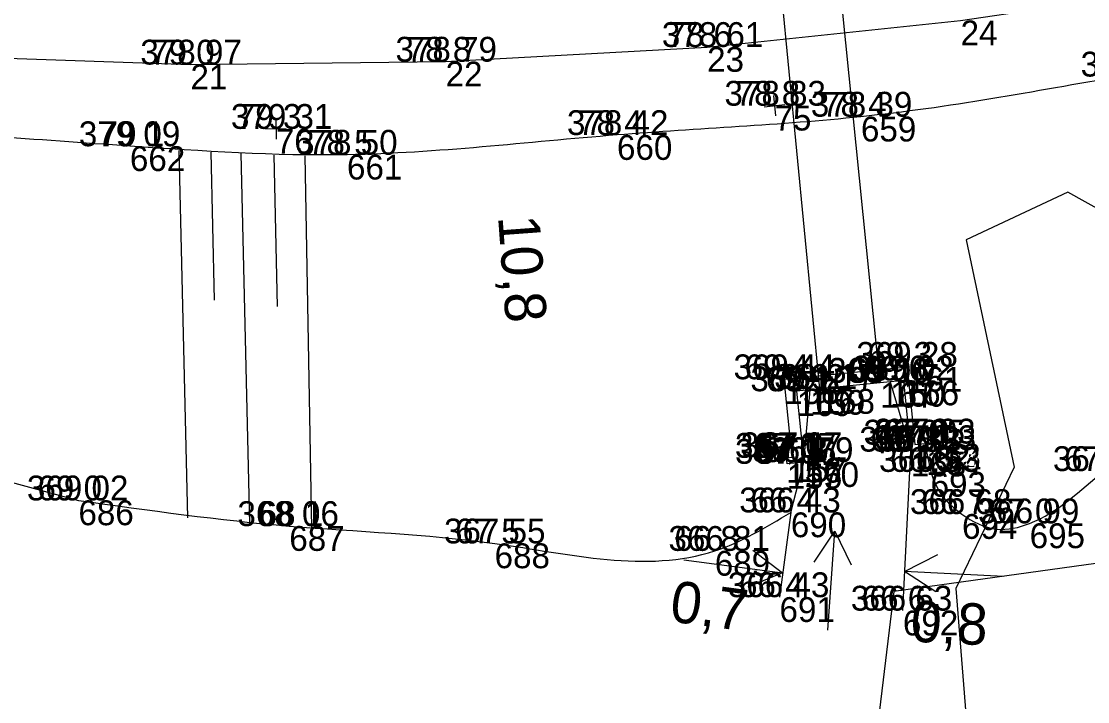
# Model space of a CAD drawing. Extents: x -514509 to -512782, y -1144610 to -1143439.
# Drawn here: x -512888.6 to -512837, y -1143668.1 to -1143635.2 of the extents above; entities that cross this region are included whole.
import ezdxf

# ---------------------------------------------------------------- set-up
doc = ezdxf.new("R2010")
doc.units = 0
for name, color, linetype in [('Vrstva 10', 7, 'Continuous'), ('Vrstva 11', 7, 'Continuous'), ('Vrstva 12', 7, 'Continuous'), ('Vrstva 35', 7, 'Continuous'), ('Vrstva 57', 7, 'Continuous'), ('Vrstva 58', 7, 'Continuous'), ('Vrstva 59', 7, 'Continuous'), ('Vrstva 6', 7, 'Continuous'), ('Vrstva 60', 7, 'Continuous'), ('Vrstva 8', 7, 'Continuous')]:
    doc.layers.add(name, color=color, linetype=linetype)

msp = doc.modelspace()

# ---------------------------------------------------------------- linework, layer by layer
at = {"layer": 'Vrstva 10'}
for p, q in [((-512853.178, -1143660.816), (-512851.751, -1143661.915)), ((-512844.324, -1143662.824), (-512845.836, -1143661.847))]:
    msp.add_line(p, q, dxfattribs=at)
for points in [[(-512782.341, -1143656.666), (-512796.89, -1143661.893), (-512815.309, -1143658.506), (-512846.358, -1143662.813), (-512847.692, -1143673.887), (-512850.552, -1143675.414), (-512874.542, -1143673.507), (-512907.663, -1143668.822), (-512937.442, -1143663.927), (-512942.033, -1143670.511), (-512944.784, -1143662.787), (-512958.978, -1143654.892), (-512977.284, -1143642.016), (-512997.25, -1143628.575), (-513034.474, -1143613.524), (-513050.89, -1143616.331), (-513050.251, -1143607.386), (-513065.331, -1143600.696), (-513084.436, -1143602.206), (-513086.215, -1143618.123), (-513093.877, -1143618.167), (-513107.772, -1143623.787)], [(-512782.341, -1143656.666), (-512796.89, -1143661.893), (-512815.309, -1143658.506), (-512846.358, -1143662.813), (-512847.692, -1143673.887), (-512850.552, -1143675.414), (-512874.542, -1143673.507), (-512907.663, -1143668.822), (-512937.442, -1143663.927), (-512942.033, -1143670.511), (-512944.784, -1143662.787), (-512958.978, -1143654.892), (-512977.284, -1143642.016), (-512997.25, -1143628.575), (-513034.474, -1143613.524), (-513050.89, -1143616.331), (-513050.251, -1143607.386), (-513065.331, -1143600.696), (-513084.436, -1143602.206), (-513086.215, -1143618.123), (-513093.877, -1143618.167), (-513107.772, -1143623.787)], [(-512880.948, -1143641.486), (-512880.52, -1143659.253)], [(-512879.401, -1143641.562), (-512879.237, -1143648.731)], [(-512877.937, -1143641.637), (-512877.524, -1143659.543)], [(-512876.35, -1143641.712), (-512876.182, -1143649.035)], [(-512874.844, -1143641.75), (-512874.529, -1143659.75)], [(-512845.919, -1143663.74), (-512845.531, -1143656.051)], [(-512845.531, -1143656.051), (-512844.799, -1143655.978)], [(-512844.799, -1143655.978), (-512844.576, -1143657.027)], [(-512851.339, -1143658.988), (-512850.718, -1143656.557)], [(-512892.217, -1143656.68), (-512885.803, -1143658.408)], [(-512851.339, -1143658.988), (-512851.888, -1143663.089)], [(-512856.509, -1143661.279), (-512851.751, -1143661.915), (-512853.417, -1143662.6)], [(-512841.043, -1143662.089), (-512845.836, -1143661.847), (-512844.233, -1143661.026)]]:
    msp.add_lwpolyline(points, dxfattribs=at)
for points in [[(-512790.897, -1143626.621), (-512793.153, -1143627.37), (-512801.979, -1143630.109), (-512814.416, -1143633.347), (-512816.803, -1143634.041), (-512819.178, -1143634.783), (-512823.981, -1143636.052), (-512829.685, -1143637.032), (-512835.405, -1143637.911), (-512841.665, -1143638.994), (-512847.953, -1143639.855), (-512859.749, -1143640.736), (-512872.808, -1143641.694), (-512883.31, -1143641.277), (-512896.82, -1143640.272), (-512913.118, -1143638.801), (-512924.825, -1143637.396), (-512937.268, -1143634.907), (-512939.41, -1143634.383), (-512941.531, -1143633.79), (-512945.755, -1143632.503)], [(-512844.576, -1143657.027), (-512844.04, -1143658.152), (-512843.598, -1143658.634), (-512843.062, -1143659.073), (-512841.392, -1143659.8), (-512839.792, -1143659.523), (-512836.217, -1143656.986), (-512830.883, -1143653.422), (-512826.439, -1143651.71), (-512824.084, -1143651.268), (-512821.716, -1143650.935), (-512819.397, -1143650.852), (-512817.055, -1143651.011), (-512814.731, -1143651.09), (-512812.465, -1143650.761), (-512801.811, -1143647.536), (-512792.751, -1143644.919), (-512786.376, -1143642.498)], [(-512885.803, -1143658.408), (-512875.601, -1143659.652), (-512865.666, -1143660.49), (-512855.017, -1143660.853), (-512851.339, -1143658.988)]]:
    msp.add_spline(points, degree=3, dxfattribs=at)
at = {"layer": 'Vrstva 12'}
for p, q in [((-512852.183, -1143638.822), (-512852.08, -1143639.817)), ((-512852.629, -1143639.371), (-512851.634, -1143639.268)), ((-512876.251, -1143639.936), (-512876.24, -1143640.935)), ((-512876.745, -1143640.441), (-512875.746, -1143640.43))]:
    msp.add_line(p, q, dxfattribs=at)
at = {"layer": 'Vrstva 35'}
msp.add_line((-512850.216, -1143661.392), (-512849.206, -1143659.901), dxfattribs=at)
msp.add_lwpolyline([(-512849.552, -1143664.689), (-512849.206, -1143659.901), (-512848.42, -1143661.522)], dxfattribs=at)
at = {"layer": 'Vrstva 6'}
for points in [[(-512853.29, -1143618.47), (-512849.95, -1143653.02)], [(-512847.02, -1143652.72), (-512850.51, -1143618.22)], [(-512923.252, -1143633.493), (-512918.011, -1143634.327), (-512906.183, -1143635.855), (-512893.885, -1143636.856), (-512880.383, -1143637.329), (-512868.04, -1143637.187), (-512855.387, -1143636.484), (-512843.127, -1143635.205), (-512831.29, -1143633.444), (-512825.879, -1143632.464), (-512813.965, -1143629.91), (-512805.054, -1143627.626), (-512792.68, -1143623.924), (-512791.757, -1143623.602)], [(-512846.533, -1143652.676), (-512845.531, -1143656.051)], [(-512850.718, -1143656.557), (-512850.413, -1143653.065)]]:
    msp.add_lwpolyline(points, dxfattribs=at)
msp.add_lwpolyline([(-512851.526, -1143656.638), (-512851.556, -1143656.349), (-512851.277, -1143656.321), (-512851.656, -1143652.552), (-512850.184, -1143652.403), (-512847.325, -1143652.116), (-512845.717, -1143651.955), (-512845.339, -1143655.71), (-512844.831, -1143655.659), (-512844.799, -1143655.978), (-512845.531, -1143656.051), (-512845.877, -1143652.607), (-512847.024, -1143652.723), (-512849.947, -1143653.017), (-512851.062, -1143653.129), (-512850.718, -1143656.557)], close=True, dxfattribs=at)
msp.add_lwpolyline([(-512851.526, -1143656.638), (-512851.556, -1143656.349), (-512851.277, -1143656.321), (-512851.656, -1143652.552), (-512850.184, -1143652.403), (-512847.325, -1143652.116), (-512845.717, -1143651.955), (-512845.339, -1143655.71), (-512844.831, -1143655.659), (-512844.799, -1143655.978), (-512845.531, -1143656.051), (-512845.877, -1143652.607), (-512847.024, -1143652.723), (-512849.947, -1143653.017), (-512851.062, -1143653.129), (-512850.718, -1143656.557)], close=True, dxfattribs=at)
at = {"layer": 'Vrstva 60'}
for p, q in [((-512855.39, -1143636.48), (-512855.39, -1143636.48)), ((-512880.38, -1143637.33), (-512880.38, -1143637.33)), ((-512868.04, -1143637.19), (-512868.04, -1143637.19)), ((-512852.13, -1143639.32), (-512852.13, -1143639.32)), ((-512847.95, -1143639.85), (-512847.95, -1143639.85)), ((-512876.25, -1143640.44), (-512876.25, -1143640.44)), ((-512859.75, -1143640.74), (-512859.75, -1143640.74)), ((-512883.31, -1143641.28), (-512883.31, -1143641.28)), ((-512872.81, -1143641.69), (-512872.81, -1143641.69)), ((-512845.72, -1143651.95), (-512845.72, -1143651.95)), ((-512851.66, -1143652.55), (-512851.66, -1143652.55)), ((-512849.95, -1143653.02), (-512849.95, -1143653.02)), ((-512847.02, -1143652.72), (-512847.02, -1143652.72)), ((-512846.533, -1143652.676), (-512846.533, -1143652.676)), ((-512845.88, -1143652.61), (-512845.88, -1143652.61)), ((-512851.06, -1143653.13), (-512851.06, -1143653.13)), ((-512850.413, -1143653.065), (-512850.413, -1143653.065)), ((-512845.53, -1143656.05), (-512845.53, -1143656.05)), ((-512845.34, -1143655.71), (-512845.34, -1143655.71)), ((-512844.83, -1143655.66), (-512844.83, -1143655.66)), ((-512844.8, -1143655.98), (-512844.8, -1143655.98)), ((-512851.56, -1143656.35), (-512851.56, -1143656.35)), ((-512851.53, -1143656.64), (-512851.53, -1143656.64)), ((-512851.28, -1143656.32), (-512851.28, -1143656.32)), ((-512850.72, -1143656.56), (-512850.72, -1143656.56)), ((-512844.58, -1143657.03), (-512844.58, -1143657.03)), ((-512885.8, -1143658.41), (-512885.8, -1143658.41)), ((-512851.34, -1143658.99), (-512851.34, -1143658.99)), ((-512843.06, -1143659.07), (-512843.06, -1143659.07)), ((-512875.6, -1143659.65), (-512875.6, -1143659.65)), ((-512839.79, -1143659.52), (-512839.79, -1143659.52)), ((-512865.67, -1143660.49), (-512865.67, -1143660.49)), ((-512855.02, -1143660.85), (-512855.02, -1143660.85)), ((-512851.89, -1143663.09), (-512851.89, -1143663.09)), ((-512845.92, -1143663.74), (-512845.92, -1143663.74))]:
    msp.add_line(p, q, dxfattribs=at)
at = {"layer": 'Vrstva 8'}
msp.add_lwpolyline([(-512817.217, -1143602.565), (-512829.577, -1143605.491), (-512829.119, -1143611.736), (-512826.292, -1143620.784), (-512828.281, -1143628.402), (-512816.231, -1143640.787), (-512816.096, -1143647.518), (-512824.494, -1143650.991), (-512837.936, -1143643.501), (-512842.862, -1143645.807), (-512840.537, -1143656.803), (-512843.361, -1143662.667), (-512842.806, -1143669.533), (-512847.692, -1143673.887), (-512850.552, -1143675.414), (-512850.702, -1143675.751)], dxfattribs=at)

# ---------------------------------------------------------------- texts
at = {"layer": 'Vrstva 11'}
for s, rotation, p in [('10,8', 274.1958, (-512865.504, -1143644.68)), ('0,7', 352.3777, (-512857.254, -1143664.25)), ('0,7', 352.3777, (-512857.254, -1143664.25)), ('0,8', 357.1135, (-512845.581, -1143665.235)), ('0,8', 357.1135, (-512845.581, -1143665.235))]:
    msp.add_text(s, height=2, rotation=rotation, dxfattribs=at).set_placement(p)
at = {"layer": 'Vrstva 57'}
for s, p in [('78 6 ', (-512857.314, -1143636.48)), ('78 8 ', (-512869.923, -1143637.19)), ('79 0 ', (-512882.334, -1143637.33)), ('78 8 ', (-512854.013, -1143639.32)), ('78 4 ', (-512849.833, -1143639.85)), ('79 3 ', (-512878.14, -1143640.44)), ('78 4 ', (-512861.633, -1143640.74)), ('79 1 ', (-512884.774, -1143641.28)), ('78 5 ', (-512874.693, -1143641.69)), ('69 3 ', (-512847.634, -1143651.95)), ('69 4 ', (-512853.574, -1143652.55)), ('69 0 ', (-512847.86, -1143652.61)), ('69 1 ', (-512852.55, -1143653.13)), ('69 2 ', (-512851.864, -1143653.02)), ('69 1 ', (-512848.51, -1143652.72)), ('67 0 ', (-512847.312, -1143655.71)), ('67 0 ', (-512846.802, -1143655.66)), ('66 8 ', (-512847.487, -1143656.05)), ('67 0 ', (-512846.772, -1143655.98)), ('67 1 ', (-512853.042, -1143656.35)), ('67 1 ', (-512853.012, -1143656.64)), ('67 1 ', (-512852.762, -1143656.32)), ('66 8 ', (-512852.677, -1143656.56)), ('66 5 ', (-512846.537, -1143657.03)), ('67 3 ', (-512838.128, -1143656.99)), ('69 0 ', (-512887.78, -1143658.41)), ('66 4 ', (-512853.297, -1143658.99)), ('66 7 ', (-512845.017, -1143659.07)), ('68 1 ', (-512877.082, -1143659.65)), ('67 0 ', (-512841.762, -1143659.52)), ('67 5 ', (-512867.578, -1143660.49)), ('66 8 ', (-512856.977, -1143660.85)), ('66 4 ', (-512853.847, -1143663.09)), ('66 6 ', (-512847.918, -1143663.74))]:
    msp.add_text(s, height=1.2, dxfattribs=at).set_placement(p)
at = {"layer": 'Vrstva 58'}
for s, p in [('378 61', (-512857.58, -1143636.48)), ('378 79', (-512870.464, -1143637.19)), ('378 97', (-512882.804, -1143637.33)), ('378 11', (-512837.321, -1143637.91)), ('378 83', (-512854.551, -1143639.32)), ('378 39', (-512850.374, -1143639.85)), ('379 31', (-512878.423, -1143640.44)), ('378 42', (-512862.171, -1143640.74)), ('379 09', (-512885.78, -1143641.28)), ('378 50', (-512875.27, -1143641.69)), ('369 28', (-512848.172, -1143651.95)), ('369 44', (-512854.112, -1143652.55)), ('369 02', (-512848.372, -1143652.61)), ('369 10', (-512853.296, -1143653.13)), ('369 17', (-512852.148, -1143653.02)), ('369 06', (-512849.536, -1143652.72)), ('367 05', (-512847.824, -1143655.71)), ('367 03', (-512847.314, -1143655.66)), ('366 83', (-512848.025, -1143656.05)), ('367 03', (-512847.284, -1143655.98)), ('367 07', (-512854.044, -1143656.35)), ('367 06', (-512854.039, -1143656.64)), ('367 07', (-512853.764, -1143656.32)), ('366 79', (-512853.218, -1143656.56)), ('366 53', (-512847.075, -1143657.03)), ('367 34', (-512838.666, -1143656.99)), ('369 02', (-512888.292, -1143658.41)), ('366 43', (-512853.835, -1143658.99)), ('366 68', (-512845.58, -1143659.07)), ('368 06', (-512878.109, -1143659.65)), ('366 99', (-512842.292, -1143659.52)), ('367 55', (-512868.116, -1143660.49)), ('366 81', (-512857.26, -1143660.85)), ('366 43', (-512854.385, -1143663.09)), ('366 63', (-512848.44, -1143663.74))]:
    msp.add_text(s, height=1.2, dxfattribs=at).set_placement(p)
at = {"layer": 'Vrstva 59'}
for s, p in [('24', (-512843.13, -1143636.4)), ('23', (-512855.39, -1143637.68)), ('21', (-512880.38, -1143638.53)), ('22', (-512868.04, -1143638.39)), ('75', (-512852.13, -1143640.52)), ('659', (-512847.95, -1143641.05)), ('76', (-512876.25, -1143641.64)), ('660', (-512859.75, -1143641.94)), ('662', (-512883.31, -1143642.48)), ('661', (-512872.81, -1143642.89)), ('161', (-512845.72, -1143653.15)), ('158', (-512851.66, -1143653.75)), ('168', (-512849.95, -1143654.22)), ('167', (-512847.02, -1143653.92)), ('160', (-512846.533, -1143653.876)), ('166', (-512845.88, -1143653.81)), ('169', (-512851.06, -1143654.33)), ('159', (-512850.413, -1143654.265)), ('165', (-512845.53, -1143657.25)), ('162', (-512845.34, -1143656.91)), ('163', (-512844.83, -1143656.86)), ('164', (-512844.8, -1143657.18)), ('156', (-512851.56, -1143657.55)), ('155', (-512851.53, -1143657.84)), ('157', (-512851.28, -1143657.52)), ('170', (-512850.72, -1143657.76)), ('693', (-512844.58, -1143658.23)), ('686', (-512885.8, -1143659.61)), ('690', (-512851.34, -1143660.19)), ('694', (-512843.06, -1143660.27)), ('687', (-512875.6, -1143660.85)), ('695', (-512839.79, -1143660.72)), ('688', (-512865.67, -1143661.69)), ('689', (-512855.02, -1143662.05)), ('691', (-512851.89, -1143664.29)), ('692', (-512845.92, -1143664.94))]:
    msp.add_text(s, height=1.2, dxfattribs=at).set_placement(p)

doc.saveas('drawing.dxf')
